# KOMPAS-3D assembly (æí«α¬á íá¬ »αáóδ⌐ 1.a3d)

Referenced files in D:\АСКОН работа\Конкурс HOME\06_Сюваев_Сборная модель танка Т90\ДЕТАЛИ\КОРПУС\МЕТАЛЛ\КОРПУС ШТАМПОВКА\БАКИ\: бак правый 1.m3d
Referenced files in D:\АСКОН работа\Конкурс HOME\06_Сюваев_Сборная модель танка Т90\ДЕТАЛИ\ОБЩИЕ ДЕТАЛИ\: ручки баков.m3d
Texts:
  Сборка бак правый 1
